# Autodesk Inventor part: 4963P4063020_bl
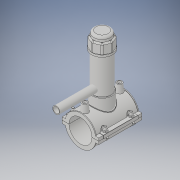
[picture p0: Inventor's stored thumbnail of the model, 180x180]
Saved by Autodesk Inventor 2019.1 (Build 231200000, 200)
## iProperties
Created: 2017-07
Part Number: 4963P4063020_bl
Material: Generic
Document SubType Name: Modeling
Designer: KIM
Density: 1 g/cm^3
Appearance: Default
Author: KIM
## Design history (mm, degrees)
derived "4963P4.ipt"
feature "Solid1::4963P4.ipt" dims "ScaleForDerivedMember" = 10
feature "Solid2::4963P4.ipt" dims "ScaleForDerivedMember" = 10
feature "Solid3::4963P4.ipt" dims "ScaleForDerivedMember" = 10
tag "TaggingFeature1"
body "Solid1"
body "Solid2"
body "Solid3"
other parameters: "d0" = 63 [user parameter], "d3" = 15.75 [user parameter], "d4" = 118 [user parameter], "d5" = 0 [user parameter], "d6" = 0.1 [user parameter], "d8" = 0 [user parameter], "d19" = 6 [user parameter], "d20" = 6 [user parameter], "d21" = 70.8 [user parameter], "d23" = 0 [user parameter], "d24" = 35.4 [user parameter], "d26" = 0 [user parameter], "d27" = 3 [user parameter], "d28" = 3 [user parameter], "d29" = 3 [user parameter], "d30" = 21 [user parameter], "d31" = 6 [user parameter], "d32" = 0 [user parameter], "d33" = 0 [user parameter], "d34" = 0.6 [user parameter], "d40" = 42.588 [user parameter], "d41" = 56.7 [user parameter], "d43" = 0 [user parameter], "d45" = 0 [user parameter], "d47" = 111.75 [user parameter], "d70" = 15 [user parameter], "d72" = 0 [user parameter], "d73" = 6 [user parameter], "d75" = 5 [user parameter], "d76" = 0 [user parameter], "d77" = 3.15 [user parameter], "d78" = 61.5 [user parameter], "d79" = 15 [user parameter], "d80" = 47.2 [user parameter], "d82" = 5 deg [user parameter], "d84" = 4 [user parameter], "d85" = 14 [user parameter], "d86" = 0 [user parameter], "d87" = 3 [user parameter], "d88" = 0 [user parameter], "d89" = 1 [user parameter], "d90" = 1 [user parameter], "d91" = 94.4 [user parameter], "d92" = 0 [user parameter], "d93" = 0.5 [user parameter], "d94" = 33.15789 [user parameter], "d96" = 83.538 [user parameter], "d97" = 2.36 [user parameter], "d98" = 0 [user parameter], "d102" = 0.63 [user parameter], "d120" = 140 deg [user parameter], "d121" = 24.228 [user parameter], "d122" = 20 deg [user parameter], "d123" = 163.8 [user parameter], "d124" = 49.14 [user parameter], "d126" = 0 [user parameter], "d143" = 64.89 [user parameter], "d145" = 14.53846 [user parameter], "d149" = 0.945 [user parameter], "d150" = 15.99231 [user parameter], "d153" = 118 [user parameter], "d154" = 0 [user parameter], "d156" = 40.95 [user parameter], "d157" = 160 deg [user parameter], "d159" = 3.78 [user parameter], "d161" = 0.945 [user parameter], "d162" = 70.8 [user parameter], "d163" = 0 [user parameter], "d164" = 31.5 [user parameter], "d167" = 6.3 [user parameter], "d168" = 39.95122 [user parameter], "d170" = 3.75 [user parameter], "d172" = 0 [user parameter], "d173" = 1 [user parameter], "d175" = 31.5 [user parameter], "d176" = 20 deg [user parameter], "d177" = 4.41 [user parameter], "d178" = 18.9 [user parameter], "d180" = 0 [user parameter], "d183" = 7.56 [user parameter], "d184" = 3.528 [user parameter], "d185" = 38.35 [user parameter], "d186" = 38.35 [user parameter], "d187" = 40.95 [user parameter], "d188" = 5.67 [user parameter], "d189" = 4.41 [user parameter], "d190" = 0 [user parameter], "d191" = 61.425 [user parameter], "d193" = 8 [user parameter], "d194" = 4.13 [user parameter], "d195" = 90 deg [user parameter], "d197" = 0 [user parameter], "d199" = 0 [user parameter], "d200" = 9.45 [user parameter], "d202" = 0 [user parameter], "d203" = 177 [user parameter], "d204" = 53.865 [user parameter], "d205" = 39.69 [user parameter], "d206" = 48.195 [user parameter], "d207" = 132.75 [user parameter], "d208" = 138.06 [user parameter], "d209" = 164.61 [user parameter], "d210" = 48.762 [user parameter], "d211" = 56.7 [user parameter], "d212" = 45.36 [user parameter], "d213" = 36 [user parameter], "d216" = 0 [user parameter], "d217" = 6.3 [user parameter], "d218" = 6.3 [user parameter], "d219" = 1.26 [user parameter], "d222" = 63 [user parameter], "d224" = 0 [user parameter], "d227" = 16 [user parameter], "d228" = 125 [user parameter], "d230" = 3.78 [user parameter], "d_" = 63 [user parameter], "L_" = 118 [user parameter], "d_t" = 6 [user parameter], "H_2" = 177 [user parameter], "H_" = 125 [user parameter]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
